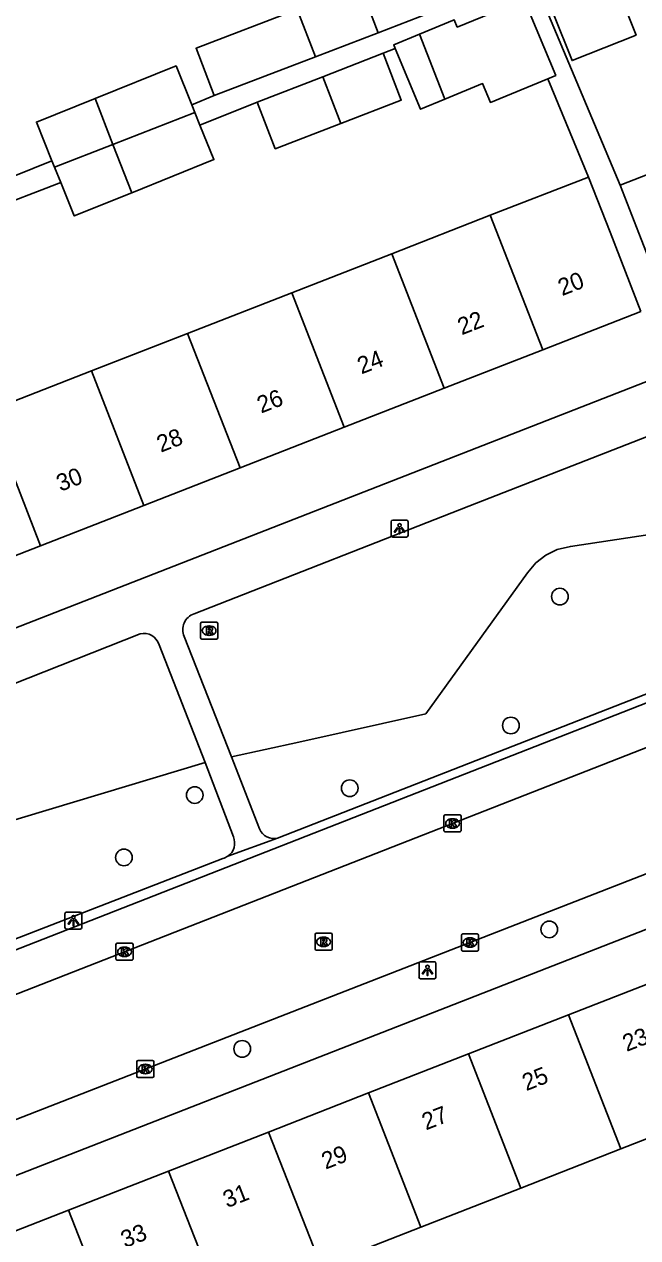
# Model space of a CAD drawing. Extents: x 159689 to 160786, y 387323 to 388339.
# Drawn here: x 160090.1 to 160126.1, y 387669.1 to 387740.3 of the extents above; entities that cross this region are included whole.
import ezdxf

# ---------------------------------------------------------------- set-up
doc = ezdxf.new("R2010")
doc.units = 0
for name, color, linetype in [('IMGEO_Boom', 7, 'Continuous'), ('IMGEO_Erf', 7, 'Continuous'), ('IMGEO_Groenvoorziening', 7, 'Continuous'), ('IMGEO_Kolk', 7, 'Continuous'), ('IMGEO_Lichtpunt', 7, 'Continuous'), ('IMGEO_Pand', 7, 'Continuous'), ('IMGEO_Pand_nummerreeks', 7, 'Continuous'), ('IMGEO_Rijbaan_lokaal_open', 7, 'Continuous'), ('IMGEO_Rioolput', 7, 'Continuous'), ('IMGEO_Voetpad_open', 7, 'Continuous')]:
    doc.layers.add(name, color=color, linetype=linetype)

msp = doc.modelspace()

# ---------------------------------------------------------------- linework, layer by layer
at = {"layer": 'IMGEO_Boom'}
for centre in [(160121.565, 387706.746), (160118.688, 387699.178), (160109.231, 387695.496), (160100.13, 387695.093), (160095.98, 387691.432), (160120.944, 387687.21), (160102.919, 387680.193)]:
    msp.add_circle(centre, 0.489, dxfattribs=at)
at = {"layer": 'IMGEO_Erf'}
for points in [[(160091.752, 387732.337), (160087.261, 387730.527)], [(160087.887, 387729.379), (160092.271, 387731.05)]]:
    msp.add_lwpolyline(points, dxfattribs=at)
at = {"layer": 'IMGEO_Groenvoorziening'}
for points in [[(160102.286, 387697.335), (160106.239, 387698.209), (160113.688, 387699.856), (160119.673, 387708.148), (160120.152, 387708.72), (160120.74, 387709.179), (160121.41, 387709.507), (160122.18, 387709.694), (160131.248, 387711.047)], [(160084.921, 387684.831), (160085.469, 387692.407), (160100.737, 387697.007)]]:
    msp.add_lwpolyline(points, dxfattribs=at)
at = {"layer": 'IMGEO_Kolk'}
for p, q in [((160114.763, 387693.002), (160114.763, 387693.854)), ((160114.838, 387693.928), (160115.69, 387693.928)), ((160115.251, 387693.708), (160115.276, 387693.708)), ((160115.764, 387693.854), (160115.764, 387693.002)), ((160115.274, 387693.148), (160115.249, 387693.148)), ((160115.69, 387692.928), (160114.838, 387692.928)), ((160115.792, 387686.012), (160115.792, 387686.864)), ((160115.867, 387686.938), (160116.719, 387686.938)), ((160116.28, 387686.718), (160116.305, 387686.718)), ((160116.793, 387686.864), (160116.793, 387686.012)), ((160095.51, 387685.467), (160095.51, 387686.319)), ((160095.585, 387686.393), (160096.437, 387686.393)), ((160095.998, 387686.173), (160096.023, 387686.173)), ((160096.511, 387686.319), (160096.511, 387685.467)), ((160116.719, 387685.938), (160115.867, 387685.938)), ((160116.303, 387686.158), (160116.278, 387686.158)), ((160096.437, 387685.393), (160095.585, 387685.393)), ((160096.021, 387685.613), (160095.996, 387685.613)), ((160096.73, 387678.588), (160096.73, 387679.44)), ((160096.805, 387679.514), (160097.657, 387679.514)), ((160097.731, 387679.44), (160097.731, 387678.588)), ((160097.241, 387678.734), (160097.216, 387678.734)), ((160097.218, 387679.294), (160097.243, 387679.294)), ((160097.657, 387678.514), (160096.805, 387678.514))]:
    msp.add_line(p, q, dxfattribs=at)
for points in [[(160114.763, 387693.002), (160114.763, 387693.854)], [(160114.838, 387693.928), (160115.69, 387693.928)], [(160115.764, 387693.854), (160115.764, 387693.002)], [(160115.084, 387693.628), (160115.207, 387693.628), (160115.207, 387693.477), (160115.337, 387693.628), (160115.501, 387693.628), (160115.355, 387693.477), (160115.508, 387693.228), (160115.356, 387693.228), (160115.271, 387693.392), (160115.207, 387693.325), (160115.207, 387693.228), (160115.084, 387693.228), (160115.084, 387693.628)], [(160115.69, 387692.928), (160114.838, 387692.928)], [(160115.792, 387686.012), (160115.792, 387686.864)], [(160115.867, 387686.938), (160116.719, 387686.938)], [(160116.113, 387686.638), (160116.236, 387686.638), (160116.236, 387686.487), (160116.366, 387686.638), (160116.53, 387686.638), (160116.384, 387686.487), (160116.537, 387686.238), (160116.385, 387686.238), (160116.3, 387686.402), (160116.236, 387686.335), (160116.236, 387686.238), (160116.113, 387686.238), (160116.113, 387686.638)], [(160116.793, 387686.864), (160116.793, 387686.012)], [(160095.51, 387685.467), (160095.51, 387686.319)], [(160095.585, 387686.393), (160096.437, 387686.393)], [(160095.831, 387686.093), (160095.954, 387686.093), (160095.954, 387685.942), (160096.084, 387686.093), (160096.248, 387686.093), (160096.102, 387685.942), (160096.255, 387685.693), (160096.103, 387685.693), (160096.018, 387685.857), (160095.954, 387685.79), (160095.954, 387685.693), (160095.831, 387685.693), (160095.831, 387686.093)], [(160096.511, 387686.319), (160096.511, 387685.467)], [(160116.719, 387685.938), (160115.867, 387685.938)], [(160096.437, 387685.393), (160095.585, 387685.393)], [(160096.73, 387678.588), (160096.73, 387679.44)], [(160096.805, 387679.514), (160097.657, 387679.514)], [(160097.731, 387679.44), (160097.731, 387678.588)], [(160097.051, 387679.214), (160097.174, 387679.214), (160097.174, 387679.063), (160097.304, 387679.214), (160097.468, 387679.214), (160097.322, 387679.063), (160097.475, 387678.814), (160097.323, 387678.814), (160097.238, 387678.978), (160097.174, 387678.911), (160097.174, 387678.814), (160097.051, 387678.814), (160097.051, 387679.214)], [(160097.657, 387678.514), (160096.805, 387678.514)]]:
    msp.add_lwpolyline(points, dxfattribs=at)
for centre, start, end in [((160114.84, 387693.852), 91.55205, 178.44795), ((160114.84, 387693.852), 91.55205, 178.44795), ((160115.688, 387693.852), 1.55205, 88.44795), ((160115.688, 387693.852), 1.55205, 88.44795), ((160114.84, 387693.004), 181.55205, 268.44795), ((160114.84, 387693.004), 181.55205, 268.44795), ((160115.688, 387693.004), 271.55205, 358.44795), ((160115.688, 387693.004), 271.55205, 358.44795), ((160115.869, 387686.862), 91.55205, 178.44795), ((160115.869, 387686.862), 91.55205, 178.44795), ((160116.717, 387686.862), 1.55205, 88.44795), ((160116.717, 387686.862), 1.55205, 88.44795), ((160095.587, 387686.317), 91.55205, 178.44795), ((160095.587, 387686.317), 91.55205, 178.44795), ((160096.435, 387686.317), 1.55205, 88.44795), ((160096.435, 387686.317), 1.55205, 88.44795), ((160115.869, 387686.014), 181.55205, 268.44795), ((160115.869, 387686.014), 181.55205, 268.44795), ((160116.717, 387686.014), 271.55205, 358.44795), ((160116.717, 387686.014), 271.55205, 358.44795), ((160095.587, 387685.469), 181.55205, 268.44795), ((160095.587, 387685.469), 181.55205, 268.44795), ((160096.435, 387685.469), 271.55205, 358.44795), ((160096.435, 387685.469), 271.55205, 358.44795), ((160096.807, 387679.438), 91.55205, 178.44795), ((160096.807, 387679.438), 91.55205, 178.44795), ((160097.655, 387679.438), 1.55205, 88.44795), ((160097.655, 387679.438), 1.55205, 88.44795), ((160096.807, 387678.59), 181.55205, 268.44795), ((160096.807, 387678.59), 181.55205, 268.44795), ((160097.655, 387678.59), 271.55205, 358.44795), ((160097.655, 387678.59), 271.55205, 358.44795)]:
    msp.add_arc(centre, 0.0765, start, end, dxfattribs=at)
for centre, major_axis, ratio, start_param, end_param in [((160115.25, 387693.428), (-0.387, 0.002), 0.722429, 4.712389, 7.853982), ((160115.275, 387693.428), (-0.39, 0.002), 0.717154, 1.570796, 4.712389), ((160116.279, 387686.438), (-0.387, 0.002), 0.722429, 4.712389, 7.853982), ((160116.304, 387686.438), (-0.39, 0.002), 0.717154, 1.570796, 4.712389), ((160095.997, 387685.893), (-0.387, 0.002), 0.722429, 4.712389, 7.853982), ((160096.022, 387685.893), (-0.39, 0.002), 0.717154, 1.570796, 4.712389), ((160097.217, 387679.014), (-0.387, 0.002), 0.722429, 4.712389, 7.853982), ((160097.242, 387679.014), (-0.39, 0.002), 0.717154, 1.570796, 4.712389)]:
    msp.add_ellipse(centre, major_axis=major_axis, ratio=ratio, start_param=start_param, end_param=end_param, dxfattribs=at)
at = {"layer": 'IMGEO_Lichtpunt'}
for p, q in [((160111.658, 387711.138), (160111.658, 387710.331)), ((160111.658, 387711.138), (160111.658, 387710.331)), ((160112.56, 387711.233), (160111.752, 387711.233)), ((160112.56, 387711.233), (160111.752, 387711.233)), ((160112.654, 387710.331), (160112.654, 387711.138)), ((160112.654, 387710.331), (160112.654, 387711.138)), ((160111.752, 387710.237), (160112.56, 387710.237)), ((160111.752, 387710.237), (160112.56, 387710.237)), ((160092.515, 387688.127), (160092.515, 387687.32)), ((160092.515, 387688.127), (160092.515, 387687.32)), ((160093.417, 387688.222), (160092.609, 387688.222)), ((160093.417, 387688.222), (160092.609, 387688.222)), ((160093.511, 387687.32), (160093.511, 387688.127)), ((160093.511, 387687.32), (160093.511, 387688.127)), ((160092.609, 387687.226), (160093.417, 387687.226)), ((160092.609, 387687.226), (160093.417, 387687.226)), ((160113.297, 387685.209), (160113.297, 387684.402)), ((160113.297, 387685.209), (160113.297, 387684.402)), ((160114.199, 387685.304), (160113.391, 387685.304)), ((160114.199, 387685.304), (160113.391, 387685.304)), ((160114.293, 387684.402), (160114.293, 387685.209)), ((160114.293, 387684.402), (160114.293, 387685.209)), ((160113.391, 387684.308), (160114.199, 387684.308)), ((160113.391, 387684.308), (160114.199, 387684.308))]:
    msp.add_line(p, q, dxfattribs=at)
for points in [[(160112.032, 387710.802), (160112.071, 387710.774), (160111.883, 387710.512), (160111.845, 387710.539), (160112.032, 387710.802)], [(160112.244, 387710.774), (160112.282, 387710.801), (160112.469, 387710.539), (160112.43, 387710.511), (160112.244, 387710.774)], [(160112.134, 387710.754), (160112.181, 387710.754), (160112.181, 387710.432), (160112.134, 387710.432), (160112.134, 387710.754)], [(160092.889, 387687.791), (160092.928, 387687.763), (160092.74, 387687.501), (160092.702, 387687.528), (160092.889, 387687.791)], [(160092.991, 387687.743), (160093.038, 387687.743), (160093.038, 387687.421), (160092.991, 387687.421), (160092.991, 387687.743)], [(160093.101, 387687.763), (160093.139, 387687.79), (160093.326, 387687.528), (160093.287, 387687.5), (160093.101, 387687.763)], [(160113.671, 387684.873), (160113.71, 387684.845), (160113.522, 387684.583), (160113.484, 387684.61), (160113.671, 387684.873)], [(160113.773, 387684.825), (160113.82, 387684.825), (160113.82, 387684.503), (160113.773, 387684.503), (160113.773, 387684.825)], [(160113.883, 387684.845), (160113.921, 387684.872), (160114.108, 387684.61), (160114.069, 387684.582), (160113.883, 387684.845)]]:
    msp.add_lwpolyline(points, dxfattribs=at)
for centre in [(160112.157, 387710.936), (160093.014, 387687.925), (160113.796, 387685.007)]:
    msp.add_circle(centre, 0.0994, dxfattribs=at)
for centre, start, end in [((160111.752, 387711.138), 90, 180), ((160111.752, 387711.138), 90, 180), ((160112.56, 387711.138), 0, 90), ((160112.56, 387711.138), 0, 90), ((160111.752, 387710.331), 180, 270), ((160111.752, 387710.331), 180, 270), ((160112.56, 387710.331), 270, 0), ((160112.56, 387710.331), 270, 360), ((160092.609, 387688.127), 90, 180), ((160092.609, 387688.127), 90, 180), ((160093.417, 387688.127), 0, 90), ((160093.417, 387688.127), 0, 90), ((160092.609, 387687.32), 180, 270), ((160092.609, 387687.32), 180, 270), ((160093.417, 387687.32), 270, 0), ((160093.417, 387687.32), 270, 360), ((160113.391, 387685.209), 90, 180), ((160113.391, 387685.209), 90, 180), ((160114.199, 387685.209), 0, 90), ((160114.199, 387685.209), 0, 90), ((160113.391, 387684.402), 180, 270), ((160113.391, 387684.402), 180, 270), ((160114.199, 387684.402), 270, 0), ((160114.199, 387684.402), 270, 360)]:
    msp.add_arc(centre, 0.0946, start, end, dxfattribs=at)
at = {"layer": 'IMGEO_Pand'}
for points in [[(160106.143, 387741.211), (160109.842, 387742.628), (160110.908, 387739.846)], [(160124.924, 387742.503), (160126.039, 387739.715), (160122.286, 387738.214), (160121.171, 387741.002)], [(160120.861, 387737.151), (160121.32, 387737.34), (160119.478, 387741.802), (160115.538, 387740.176), (160115.361, 387740.604), (160113.332, 387739.766)], [(160101.277, 387736.156), (160100.211, 387738.938), (160106.143, 387741.211)], [(160107.223, 387738.434), (160106.143, 387741.211)], [(160110.908, 387739.846), (160107.223, 387738.434)], [(160113.332, 387739.766), (160111.816, 387739.141), (160111.902, 387738.932)], [(160114.82, 387735.954), (160113.332, 387739.766)], [(160107.647, 387737.267), (160111.197, 387738.641)], [(160111.197, 387738.641), (160112.258, 387735.896), (160108.717, 387734.525)], [(160111.902, 387738.932), (160113.377, 387735.359), (160114.82, 387735.954)], [(160099.957, 387735.624), (160099.037, 387737.905), (160094.284, 387735.988)], [(160107.223, 387738.434), (160101.277, 387736.156)], [(160103.801, 387735.779), (160107.647, 387737.267)], [(160107.647, 387737.267), (160108.717, 387734.525)], [(160114.82, 387735.954), (160117.032, 387736.867), (160117.49, 387735.759), (160120.861, 387737.151)], [(160094.284, 387735.988), (160090.84, 387734.599), (160091.752, 387732.337)], [(160094.284, 387735.988), (160095.33, 387733.293)], [(160108.717, 387734.525), (160104.863, 387733.034), (160103.801, 387735.779)], [(160095.33, 387733.293), (160100.144, 387735.159)], [(160100.144, 387735.159), (160099.957, 387735.624)], [(160100.441, 387734.423), (160100.144, 387735.159)], [(160096.437, 387730.457), (160101.257, 387732.401), (160100.441, 387734.423)], [(160091.902, 387731.964), (160095.33, 387733.293)], [(160096.437, 387730.457), (160095.33, 387733.293)], [(160125.095, 387730.896), (160131.174, 387733.276)], [(160091.902, 387731.964), (160091.752, 387732.337)], [(160092.271, 387731.05), (160091.902, 387731.964)], [(160092.271, 387731.05), (160093.06, 387729.095), (160096.437, 387730.457)], [(160117.482, 387729.131), (160123.244, 387731.379)], [(160123.244, 387731.379), (160124.508, 387728.141), (160126.325, 387723.483)], [(160128.155, 387723.079), (160126.332, 387727.735), (160125.095, 387730.896)], [(160111.702, 387726.875), (160117.482, 387729.131)], [(160117.482, 387729.131), (160120.563, 387721.235)], [(160105.825, 387724.582), (160111.702, 387726.875)], [(160114.783, 387718.979), (160111.702, 387726.875)], [(160099.711, 387722.196), (160105.825, 387724.582)], [(160108.906, 387716.686), (160105.825, 387724.582)], [(160126.325, 387723.483), (160120.563, 387721.235)], [(160094.072, 387719.995), (160099.711, 387722.196)], [(160099.711, 387722.196), (160102.792, 387714.3)], [(160120.563, 387721.235), (160114.783, 387718.979)], [(160088.005, 387717.628), (160094.072, 387719.995)], [(160097.153, 387712.099), (160094.072, 387719.995)], [(160114.783, 387718.979), (160108.906, 387716.686)], [(160091.086, 387709.732), (160088.005, 387717.628)], [(160108.906, 387716.686), (160102.792, 387714.3)], [(160102.792, 387714.3), (160097.153, 387712.099)], [(160097.153, 387712.099), (160091.086, 387709.732)], [(160091.086, 387709.732), (160085.158, 387707.419)], [(160122.067, 387682.196), (160127.934, 387684.49)], [(160116.199, 387679.901), (160122.067, 387682.196)], [(160122.067, 387682.196), (160125.148, 387674.318)], [(160110.333, 387677.607), (160116.199, 387679.901)], [(160116.199, 387679.901), (160119.281, 387672.023)], [(160104.465, 387675.312), (160110.333, 387677.607)], [(160113.414, 387669.729), (160110.333, 387677.607)], [(160131.015, 387676.612), (160125.148, 387674.318)], [(160098.597, 387673.017), (160104.465, 387675.312)], [(160107.546, 387667.434), (160104.465, 387675.312)], [(160125.148, 387674.318), (160119.281, 387672.023)], [(160092.73, 387670.723), (160098.597, 387673.017)], [(160098.597, 387673.017), (160101.679, 387665.139)], [(160119.281, 387672.023), (160113.414, 387669.729)], [(160086.863, 387668.428), (160092.73, 387670.723)], [(160095.811, 387662.844), (160092.73, 387670.723)], [(160113.414, 387669.729), (160107.546, 387667.434)]]:
    msp.add_lwpolyline(points, dxfattribs=at)
at = {"layer": 'IMGEO_Rijbaan_lokaal_open'}
for points in [[(160182.985, 387719.864), (160133.651, 387700.624), (160089.312, 387683.27), (160055.434, 387670.196)], [(160190, 387715.208), (160155.133, 387701.581), (160119.003, 387687.495), (160085.401, 387674.408), (160057.185, 387663.329)]]:
    msp.add_lwpolyline(points, dxfattribs=at)
at = {"layer": 'IMGEO_Rioolput'}
for p, q in [((160100.478, 387704.321), (160100.478, 387705.173)), ((160100.553, 387705.247), (160101.405, 387705.247)), ((160101.479, 387705.173), (160101.479, 387704.321)), ((160100.989, 387704.467), (160100.964, 387704.467)), ((160100.966, 387705.027), (160100.991, 387705.027)), ((160101.405, 387704.247), (160100.553, 387704.247)), ((160107.196, 387686.053), (160107.196, 387686.905)), ((160107.271, 387686.979), (160108.123, 387686.979)), ((160107.684, 387686.759), (160107.709, 387686.759)), ((160108.197, 387686.905), (160108.197, 387686.053)), ((160108.123, 387685.979), (160107.271, 387685.979)), ((160107.707, 387686.199), (160107.682, 387686.199))]:
    msp.add_line(p, q, dxfattribs=at)
for points in [[(160100.478, 387704.321), (160100.478, 387705.173)], [(160100.553, 387705.247), (160101.405, 387705.247)], [(160101.479, 387705.173), (160101.479, 387704.321)], [(160101.067, 387704.945), (160100.815, 387704.947), (160100.815, 387704.547)], [(160100.815, 387704.547), (160100.939, 387704.547), (160100.939, 387704.709), (160100.95, 387704.709)], [(160100.993, 387704.866), (160100.939, 387704.866), (160100.939, 387704.785)], [(160100.939, 387704.785), (160100.991, 387704.785)], [(160100.997, 387704.68), (160101.068, 387704.547), (160101.208, 387704.547), (160101.143, 387704.673)], [(160101.405, 387704.247), (160100.553, 387704.247)], [(160107.196, 387686.053), (160107.196, 387686.905)], [(160107.271, 387686.979), (160108.123, 387686.979)], [(160107.785, 387686.677), (160107.533, 387686.679), (160107.533, 387686.279)], [(160107.711, 387686.598), (160107.657, 387686.598), (160107.657, 387686.517)], [(160108.197, 387686.905), (160108.197, 387686.053)], [(160108.123, 387685.979), (160107.271, 387685.979)], [(160107.533, 387686.279), (160107.657, 387686.279), (160107.657, 387686.441), (160107.668, 387686.441)], [(160107.657, 387686.517), (160107.709, 387686.517)], [(160107.715, 387686.412), (160107.786, 387686.279), (160107.926, 387686.279), (160107.861, 387686.405)]]:
    msp.add_lwpolyline(points, dxfattribs=at)
for centre, radius, start, end in [((160100.555, 387705.171), 0.0765, 91.55205, 178.44795), ((160100.555, 387705.171), 0.0765, 91.55205, 178.44795), ((160101.403, 387705.171), 0.0765, 1.55205, 88.44795), ((160101.403, 387705.171), 0.0765, 1.55205, 88.44795), ((160100.949, 387704.656), 0.0533, 26.02933, 88.69889), ((160100.975, 387704.974), 0.19, 274.7715, 282.96867), ((160100.999, 387704.77), 0.0964, 77.00612, 93.18647), ((160101.013, 387704.827), 0.0378, 276.66336, 79.67722), ((160101.066, 387704.835), 0.109, 350.36119, 89.41601), ((160101.064, 387704.835), 0.112, 277.58423, 350.98172), ((160101.048, 387704.62), 0.108, 29.51342, 73.79051), ((160100.555, 387704.323), 0.0765, 181.55205, 268.44795), ((160100.555, 387704.323), 0.0765, 181.55205, 268.44795), ((160101.403, 387704.323), 0.0765, 271.55205, 358.44795), ((160101.403, 387704.323), 0.0765, 271.55205, 358.44795), ((160107.273, 387686.903), 0.0765, 91.55205, 178.44795), ((160107.273, 387686.903), 0.0765, 91.55205, 178.44795), ((160107.717, 387686.502), 0.0964, 77.00612, 93.18647), ((160107.731, 387686.559), 0.0378, 276.66336, 79.67722), ((160107.784, 387686.567), 0.109, 350.36119, 89.41601), ((160107.782, 387686.567), 0.112, 277.58423, 350.98172), ((160108.121, 387686.903), 0.0765, 1.55205, 88.44795), ((160108.121, 387686.903), 0.0765, 1.55205, 88.44795), ((160107.273, 387686.055), 0.0765, 181.55205, 268.44795), ((160107.273, 387686.055), 0.0765, 181.55205, 268.44795), ((160107.667, 387686.388), 0.0533, 26.02933, 88.69889), ((160107.693, 387686.706), 0.19, 274.7715, 282.96867), ((160107.766, 387686.352), 0.108, 29.51342, 73.79051), ((160108.121, 387686.055), 0.0765, 271.55205, 358.44795), ((160108.121, 387686.055), 0.0765, 271.55205, 358.44795)]:
    msp.add_arc(centre, radius, start, end, dxfattribs=at)
for centre, major_axis, ratio, start_param, end_param in [((160100.965, 387704.747), (-0.387, 0.002), 0.722429, 4.712389, 7.853982), ((160100.99, 387704.747), (-0.39, 0.002), 0.717154, 1.570796, 4.712389), ((160107.683, 387686.479), (-0.387, 0.002), 0.722429, 4.712389, 7.853982), ((160107.708, 387686.479), (-0.39, 0.002), 0.717154, 1.570796, 4.712389)]:
    msp.add_ellipse(centre, major_axis=major_axis, ratio=ratio, start_param=start_param, end_param=end_param, dxfattribs=at)
at = {"layer": 'IMGEO_Voetpad_open'}
for points in [[(160115.136, 387741.493), (160110.908, 387739.846)], [(160121.171, 387741.002), (160120.902, 387740.895), (160125.095, 387730.896)], [(160111.197, 387738.641), (160111.902, 387738.932)], [(160120.861, 387737.151), (160123.244, 387731.379)], [(160101.277, 387736.156), (160099.957, 387735.624)], [(160100.441, 387734.423), (160103.801, 387735.779)], [(160057.664, 387673.563), (160058.019, 387673.764), (160088.425, 387685.547), (160132.762, 387702.9), (160185.066, 387723.299)], [(160127.764, 387719.796), (160068.881, 387696.811)], [(160100.09, 387705.736), (160116.68, 387712.231), (160128.251, 387716.753)], [(160077.39, 387696.839), (160081.886, 387698.615), (160096.924, 387704.562)], [(160102.286, 387697.335), (160099.519, 387704.401)], [(160098.038, 387703.91), (160100.737, 387697.007)], [(160132.975, 387703.497), (160105, 387692.567)], [(160103.941, 387693.11), (160102.286, 387697.335)], [(160100.737, 387697.007), (160102.4, 387692.643)], [(160105, 387692.567), (160102.074, 387691.504)], [(160079.902, 387668.962), (160138.693, 387691.913)], [(160101.779, 387691.369), (160084.921, 387684.831)]]:
    msp.add_lwpolyline(points, dxfattribs=at)
for centre, radius, start, end in [((160100.411, 387704.809), 0.981, 109.07952, 204.6062), ((160097.148, 387703.666), 0.923, 15.30818, 104.01279), ((160104.788, 387693.457), 0.915, 202.30375, 283.40348), ((160101.539, 387692.273), 0.937, 304.80288, 23.25319), ((160101.528, 387692.306), 0.97, 284.96641, 304.21382)]:
    msp.add_arc(centre, radius, start, end, dxfattribs=at)

# ---------------------------------------------------------------- texts
at = {"layer": 'IMGEO_Pand_nummerreeks'}
for s, rotation, p in [('20', 21.31715, (160121.697, 387724.383)), ('22', 21.31715, (160115.804, 387722.083)), ('24', 21.31715, (160109.918, 387719.786)), ('26', 21.31715, (160104.03, 387717.488)), ('28', 21.31715, (160098.143, 387715.191)), ('30', 21.31715, (160092.254, 387712.893)), ('23', 21.35995, (160125.483, 387680.011)), ('25', 21.35995, (160119.593, 387677.707)), ('27', 21.35995, (160113.704, 387675.404)), ('29', 21.35995, (160107.814, 387673.1)), ('31', 21.35995, (160102.029, 387670.838)), ('33', 21.35995, (160096.035, 387668.494))]:
    msp.add_text(s, height=1, rotation=rotation, dxfattribs=at).set_placement(p)

doc.saveas('drawing.dxf')
